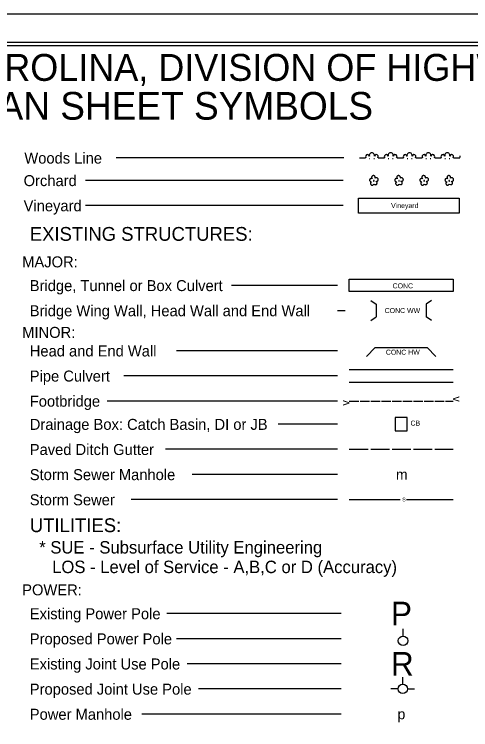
# Model space of a CAD drawing. Extents: x 2078953 to 2080637, y 324331 to 325431.
# Drawn here: x 2079876 to 2080239, y 324862 to 325431 of the extents above; entities that cross this region are included whole.
import ezdxf

# ---------------------------------------------------------------- set-up
doc = ezdxf.new("R2010")
doc.units = 0
for name, color, linetype in [('Sheet Cutting Line CELL', 7, 'Continuous'), ('Sheet Plot Border Inside CELL', 7, 'Continuous'), ('Sheet Plot Border Outside CELL', 7, 'Continuous'), ('Sheet Symbology CELL', 7, 'Continuous')]:
    doc.layers.add(name, color=color, linetype=linetype)

msp = doc.modelspace()

# ---------------------------------------------------------------- linework, layer by layer
at = {"layer": 'Sheet Cutting Line CELL'}
msp.add_line((2080636.7, 325431.07), (2078952.7, 325431.07), dxfattribs=at)
at = {"layer": 'Sheet Plot Border Inside CELL'}
msp.add_lwpolyline([(2078965.7, 324353.52), (2080632.2, 324353.52), (2080632.2, 325408.62), (2078965.7, 325408.62)], close=True, dxfattribs=at)
at = {"layer": 'Sheet Plot Border Outside CELL'}
msp.add_lwpolyline([(2078952.7, 324331.07), (2080636.7, 324331.07), (2080636.7, 325431.07), (2078952.7, 325431.07)], close=True, dxfattribs=at)
at = {"layer": 'Sheet Symbology CELL'}
for p, q in [((2080137.96, 325316.8), (2079956.83, 325316.8)), ((2080150.35, 325316.8), (2080155.35, 325316.8)), ((2080158.3, 325316.3), (2080158.8, 325316.3)), ((2080161.8, 325316.3), (2080162.3, 325316.3)), ((2080165.35, 325316.8), (2080170.35, 325316.8)), ((2080173.3, 325316.3), (2080173.8, 325316.3)), ((2080176.8, 325316.3), (2080177.3, 325316.3)), ((2080180.35, 325316.8), (2080185.35, 325316.8)), ((2080188.3, 325316.3), (2080188.8, 325316.3)), ((2080191.8, 325316.3), (2080192.3, 325316.3)), ((2080195.35, 325316.8), (2080200.35, 325316.8)), ((2080203.3, 325316.3), (2080203.8, 325316.3)), ((2080206.8, 325316.3), (2080207.3, 325316.3)), ((2080210.35, 325316.8), (2080215.35, 325316.8)), ((2080218.3, 325316.3), (2080218.8, 325316.3)), ((2080221.8, 325316.3), (2080222.3, 325316.3)), ((2080225.35, 325316.8), (2080230.35, 325316.8)), ((2080137.39, 325298.87), (2079932.46, 325298.87)), ((2080137.39, 325278.87), (2079932.46, 325278.87)), ((2080133.08, 325215.37), (2080048.65, 325215.37)), ((2080159.53, 325203.23), (2080163.63, 325200.37)), ((2080163.63, 325200.37), (2080163.63, 325190.37)), ((2080207.73, 325203.23), (2080203.63, 325200.37)), ((2080203.63, 325200.37), (2080203.63, 325190.37)), ((2080133.08, 325195.37), (2080139.07, 325195.37)), ((2080159.53, 325187.5), (2080163.63, 325190.37)), ((2080207.73, 325187.5), (2080203.63, 325190.37)), ((2080133.08, 325163.37), (2080004.78, 325163.37)), ((2080155.93, 325158.8), (2080163, 325165.87)), ((2080163, 325165.87), (2080204.25, 325165.87)), ((2080204.25, 325165.87), (2080211.33, 325158.8)), ((2080142.38, 325148.37), (2080224.88, 325148.37)), ((2080133.08, 325143.37), (2079962.89, 325143.37)), ((2080142.38, 325138.37), (2080224.88, 325138.37)), ((2080133.08, 325123.37), (2079949.6, 325123.37)), ((2080142.38, 325123.37), (2080149.88, 325123.37)), ((2080150.88, 325123.37), (2080158.38, 325123.37)), ((2080159.38, 325123.37), (2080166.88, 325123.37)), ((2080167.88, 325123.37), (2080175.38, 325123.37)), ((2080176.38, 325123.37), (2080183.88, 325123.37)), ((2080184.88, 325123.37), (2080192.38, 325123.37)), ((2080193.38, 325123.37), (2080200.88, 325123.37)), ((2080201.88, 325123.37), (2080209.38, 325123.37)), ((2080210.38, 325123.37), (2080217.88, 325123.37)), ((2080218.88, 325123.37), (2080224.88, 325123.37)), ((2080133.08, 325104.94), (2080085.88, 325104.94)), ((2080133.08, 325084.94), (2079996.13, 325084.94)), ((2080142.38, 325084.94), (2080157.38, 325084.94)), ((2080159.38, 325084.94), (2080174.38, 325084.94)), ((2080176.38, 325084.94), (2080191.38, 325084.94)), ((2080193.38, 325084.94), (2080208.38, 325084.94)), ((2080210.38, 325084.94), (2080224.88, 325084.94)), ((2080133.08, 325064.94), (2080017.4, 325064.94)), ((2080133.08, 325044.94), (2079968.88, 325044.94)), ((2080142.38, 325044.94), (2080182.9, 325044.94)), ((2080187.9, 325044.94), (2080224.88, 325044.94)), ((2080135.87, 324954.25), (2079997.17, 324954.25)), ((2080185.09, 324936.37), (2080185.09, 324941.99)), ((2080135.87, 324934.25), (2080004.95, 324934.25)), ((2080135.87, 324914.25), (2080013.35, 324914.25)), ((2080184.88, 324898.02), (2080184.88, 324903.64)), ((2080135.87, 324894.25), (2080022.35, 324894.25)), ((2080181.13, 324894.27), (2080175.5, 324894.27)), ((2080188.63, 324894.27), (2080194.25, 324894.27)), ((2080135.87, 324874.25), (2079977.37, 324874.25))]:
    msp.add_line(p, q, dxfattribs=at)
for points in [[(2080619.7, 325406.07), (2079119.7, 325406.07), (2079119.7, 324357.08), (2080619.7, 324357.08)], [(2080178.82, 325099.62), (2080188.43, 325099.62), (2080188.43, 325110.26), (2080178.82, 325110.26)]]:
    msp.add_lwpolyline(points, close=True, dxfattribs=at)
for points in [[(2080162.84, 325300.62), (2080162.99, 325300.92), (2080163.04, 325301.22), (2080162.99, 325301.52), (2080162.94, 325301.82), (2080162.79, 325302.07), (2080162.64, 325302.32), (2080162.39, 325302.52), (2080162.14, 325302.67), (2080161.79, 325302.77), (2080161.54, 325302.77), (2080161.24, 325302.72), (2080160.94, 325302.62), (2080160.69, 325302.47), (2080160.44, 325302.27), (2080160.29, 325301.97), (2080160.19, 325301.72), (2080160.14, 325301.42), (2080160.14, 325301.12), (2080160.19, 325300.82), (2080160.34, 325300.57), (2080160.54, 325300.27), (2080160.29, 325300.42), (2080159.99, 325300.47), (2080159.69, 325300.47), (2080159.44, 325300.37), (2080159.19, 325300.27), (2080158.94, 325300.07), (2080158.74, 325299.87), (2080158.59, 325299.62), (2080158.54, 325299.37), (2080158.49, 325299.02), (2080158.54, 325298.77), (2080158.64, 325298.52), (2080158.84, 325298.27), (2080158.99, 325298.07), (2080159.24, 325297.92), (2080159.54, 325297.77), (2080159.79, 325297.72), (2080160.09, 325297.72), (2080159.84, 325297.62), (2080159.59, 325297.42), (2080159.44, 325297.22), (2080159.34, 325296.92), (2080159.24, 325296.62), (2080159.24, 325296.37), (2080159.29, 325296.07), (2080159.44, 325295.82), (2080159.59, 325295.57), (2080159.79, 325295.37), (2080160.04, 325295.22), (2080160.29, 325295.12), (2080160.59, 325295.12), (2080160.89, 325295.12), (2080161.14, 325295.17), (2080161.39, 325295.37), (2080161.64, 325295.52), (2080161.89, 325295.97)], [(2080161.99, 325298.87), (2080161.84, 325298.87), (2080161.74, 325298.82), (2080161.64, 325298.77), (2080161.64, 325298.62), (2080161.64, 325298.52), (2080161.74, 325298.42), (2080161.89, 325298.42), (2080161.99, 325298.42), (2080162.09, 325298.52), (2080162.14, 325298.67), (2080162.09, 325298.77), (2080161.99, 325298.87)], [(2080161.89, 325295.97), (2080162.49, 325295.62), (2080162.79, 325295.52), (2080163.09, 325295.47), (2080163.39, 325295.52), (2080163.64, 325295.62), (2080163.89, 325295.77), (2080164.14, 325295.97), (2080164.29, 325296.22), (2080164.39, 325296.47), (2080164.49, 325296.77), (2080164.44, 325297.07), (2080164.39, 325297.37), (2080164.19, 325297.67), (2080164.04, 325297.87), (2080163.79, 325298.02), (2080163.49, 325298.17), (2080163.79, 325298.12), (2080164.14, 325298.12), (2080164.39, 325298.22), (2080164.69, 325298.37), (2080164.94, 325298.52), (2080165.14, 325298.77), (2080165.29, 325299.07), (2080165.34, 325299.37), (2080165.39, 325299.67), (2080165.34, 325299.97), (2080165.24, 325300.27), (2080165.04, 325300.52), (2080164.79, 325300.77), (2080164.54, 325300.92), (2080164.24, 325301.02), (2080163.94, 325301.07), (2080163.64, 325301.07), (2080163.34, 325300.97), (2080163.09, 325300.82), (2080162.84, 325300.62)], [(2080182.84, 325300.62), (2080182.99, 325300.92), (2080183.04, 325301.22), (2080182.99, 325301.52), (2080182.94, 325301.82), (2080182.79, 325302.07), (2080182.64, 325302.32), (2080182.39, 325302.52), (2080182.14, 325302.67), (2080181.79, 325302.77), (2080181.54, 325302.77), (2080181.24, 325302.72), (2080180.94, 325302.62), (2080180.69, 325302.47), (2080180.44, 325302.27), (2080180.29, 325301.97), (2080180.19, 325301.72), (2080180.14, 325301.42), (2080180.14, 325301.12), (2080180.19, 325300.82), (2080180.34, 325300.57), (2080180.54, 325300.27), (2080180.29, 325300.42), (2080179.99, 325300.47), (2080179.69, 325300.47), (2080179.44, 325300.37), (2080179.19, 325300.27), (2080178.94, 325300.07), (2080178.74, 325299.87), (2080178.59, 325299.62), (2080178.54, 325299.37), (2080178.49, 325299.02), (2080178.54, 325298.77), (2080178.64, 325298.52), (2080178.84, 325298.27), (2080178.99, 325298.07), (2080179.24, 325297.92), (2080179.54, 325297.77), (2080179.79, 325297.72), (2080180.09, 325297.72), (2080179.84, 325297.62), (2080179.59, 325297.42), (2080179.44, 325297.22), (2080179.34, 325296.92), (2080179.24, 325296.62), (2080179.24, 325296.37), (2080179.29, 325296.07), (2080179.44, 325295.82), (2080179.59, 325295.57), (2080179.79, 325295.37), (2080180.04, 325295.22), (2080180.29, 325295.12), (2080180.59, 325295.12), (2080180.89, 325295.12), (2080181.14, 325295.17), (2080181.39, 325295.37), (2080181.64, 325295.52), (2080181.89, 325295.97)], [(2080181.99, 325298.87), (2080181.84, 325298.87), (2080181.74, 325298.82), (2080181.64, 325298.77), (2080181.64, 325298.62), (2080181.64, 325298.52), (2080181.74, 325298.42), (2080181.89, 325298.42), (2080181.99, 325298.42), (2080182.09, 325298.52), (2080182.14, 325298.67), (2080182.09, 325298.77), (2080181.99, 325298.87)], [(2080181.89, 325295.97), (2080182.49, 325295.62), (2080182.79, 325295.52), (2080183.09, 325295.47), (2080183.39, 325295.52), (2080183.64, 325295.62), (2080183.89, 325295.77), (2080184.14, 325295.97), (2080184.29, 325296.22), (2080184.39, 325296.47), (2080184.49, 325296.77), (2080184.44, 325297.07), (2080184.39, 325297.37), (2080184.19, 325297.67), (2080184.04, 325297.87), (2080183.79, 325298.02), (2080183.49, 325298.17), (2080183.79, 325298.12), (2080184.14, 325298.12), (2080184.39, 325298.22), (2080184.69, 325298.37), (2080184.94, 325298.52), (2080185.14, 325298.77), (2080185.29, 325299.07), (2080185.34, 325299.37), (2080185.39, 325299.67), (2080185.34, 325299.97), (2080185.24, 325300.27), (2080185.04, 325300.52), (2080184.79, 325300.77), (2080184.54, 325300.92), (2080184.24, 325301.02), (2080183.94, 325301.07), (2080183.64, 325301.07), (2080183.34, 325300.97), (2080183.09, 325300.82), (2080182.84, 325300.62)], [(2080202.84, 325300.62), (2080202.99, 325300.92), (2080203.04, 325301.22), (2080202.99, 325301.52), (2080202.94, 325301.82), (2080202.79, 325302.07), (2080202.64, 325302.32), (2080202.39, 325302.52), (2080202.14, 325302.67), (2080201.79, 325302.77), (2080201.54, 325302.77), (2080201.24, 325302.72), (2080200.94, 325302.62), (2080200.69, 325302.47), (2080200.44, 325302.27), (2080200.29, 325301.97), (2080200.19, 325301.72), (2080200.14, 325301.42), (2080200.14, 325301.12), (2080200.19, 325300.82), (2080200.34, 325300.57), (2080200.54, 325300.27), (2080200.29, 325300.42), (2080199.99, 325300.47), (2080199.69, 325300.47), (2080199.44, 325300.37), (2080199.19, 325300.27), (2080198.94, 325300.07), (2080198.74, 325299.87), (2080198.59, 325299.62), (2080198.54, 325299.37), (2080198.49, 325299.02), (2080198.54, 325298.77), (2080198.64, 325298.52), (2080198.84, 325298.27), (2080198.99, 325298.07), (2080199.24, 325297.92), (2080199.54, 325297.77), (2080199.79, 325297.72), (2080200.09, 325297.72), (2080199.84, 325297.62), (2080199.59, 325297.42), (2080199.44, 325297.22), (2080199.34, 325296.92), (2080199.24, 325296.62), (2080199.24, 325296.37), (2080199.29, 325296.07), (2080199.44, 325295.82), (2080199.59, 325295.57), (2080199.79, 325295.37), (2080200.04, 325295.22), (2080200.29, 325295.12), (2080200.59, 325295.12), (2080200.89, 325295.12), (2080201.14, 325295.17), (2080201.39, 325295.37), (2080201.64, 325295.52), (2080201.89, 325295.97)], [(2080201.99, 325298.87), (2080201.84, 325298.87), (2080201.74, 325298.82), (2080201.64, 325298.77), (2080201.64, 325298.62), (2080201.64, 325298.52), (2080201.74, 325298.42), (2080201.89, 325298.42), (2080201.99, 325298.42), (2080202.09, 325298.52), (2080202.14, 325298.67), (2080202.09, 325298.77), (2080201.99, 325298.87)], [(2080201.89, 325295.97), (2080202.49, 325295.62), (2080202.79, 325295.52), (2080203.09, 325295.47), (2080203.39, 325295.52), (2080203.64, 325295.62), (2080203.89, 325295.77), (2080204.14, 325295.97), (2080204.29, 325296.22), (2080204.39, 325296.47), (2080204.49, 325296.77), (2080204.44, 325297.07), (2080204.39, 325297.37), (2080204.19, 325297.67), (2080204.04, 325297.87), (2080203.79, 325298.02), (2080203.49, 325298.17), (2080203.79, 325298.12), (2080204.14, 325298.12), (2080204.39, 325298.22), (2080204.69, 325298.37), (2080204.94, 325298.52), (2080205.14, 325298.77), (2080205.29, 325299.07), (2080205.34, 325299.37), (2080205.39, 325299.67), (2080205.34, 325299.97), (2080205.24, 325300.27), (2080205.04, 325300.52), (2080204.79, 325300.77), (2080204.54, 325300.92), (2080204.24, 325301.02), (2080203.94, 325301.07), (2080203.64, 325301.07), (2080203.34, 325300.97), (2080203.09, 325300.82), (2080202.84, 325300.62)], [(2080222.84, 325300.62), (2080222.99, 325300.92), (2080223.04, 325301.22), (2080222.99, 325301.52), (2080222.94, 325301.82), (2080222.79, 325302.07), (2080222.64, 325302.32), (2080222.39, 325302.52), (2080222.14, 325302.67), (2080221.79, 325302.77), (2080221.54, 325302.77), (2080221.24, 325302.72), (2080220.94, 325302.62), (2080220.69, 325302.47), (2080220.44, 325302.27), (2080220.29, 325301.97), (2080220.19, 325301.72), (2080220.14, 325301.42), (2080220.14, 325301.12), (2080220.19, 325300.82), (2080220.34, 325300.57), (2080220.54, 325300.27), (2080220.29, 325300.42), (2080219.99, 325300.47), (2080219.69, 325300.47), (2080219.44, 325300.37), (2080219.19, 325300.27), (2080218.94, 325300.07), (2080218.74, 325299.87), (2080218.59, 325299.62), (2080218.54, 325299.37), (2080218.49, 325299.02), (2080218.54, 325298.77), (2080218.64, 325298.52), (2080218.84, 325298.27), (2080218.99, 325298.07), (2080219.24, 325297.92), (2080219.54, 325297.77), (2080219.79, 325297.72), (2080220.09, 325297.72), (2080219.84, 325297.62), (2080219.59, 325297.42), (2080219.44, 325297.22), (2080219.34, 325296.92), (2080219.24, 325296.62), (2080219.24, 325296.37), (2080219.29, 325296.07), (2080219.44, 325295.82), (2080219.59, 325295.57), (2080219.79, 325295.37), (2080220.04, 325295.22), (2080220.29, 325295.12), (2080220.59, 325295.12), (2080220.89, 325295.12), (2080221.14, 325295.17), (2080221.39, 325295.37), (2080221.64, 325295.52), (2080221.89, 325295.97)], [(2080221.99, 325298.87), (2080221.84, 325298.87), (2080221.74, 325298.82), (2080221.64, 325298.77), (2080221.64, 325298.62), (2080221.64, 325298.52), (2080221.74, 325298.42), (2080221.89, 325298.42), (2080221.99, 325298.42), (2080222.09, 325298.52), (2080222.14, 325298.67), (2080222.09, 325298.77), (2080221.99, 325298.87)], [(2080221.89, 325295.97), (2080222.49, 325295.62), (2080222.79, 325295.52), (2080223.09, 325295.47), (2080223.39, 325295.52), (2080223.64, 325295.62), (2080223.89, 325295.77), (2080224.14, 325295.97), (2080224.29, 325296.22), (2080224.39, 325296.47), (2080224.49, 325296.77), (2080224.44, 325297.07), (2080224.39, 325297.37), (2080224.19, 325297.67), (2080224.04, 325297.87), (2080223.79, 325298.02), (2080223.49, 325298.17), (2080223.79, 325298.12), (2080224.14, 325298.12), (2080224.39, 325298.22), (2080224.69, 325298.37), (2080224.94, 325298.52), (2080225.14, 325298.77), (2080225.29, 325299.07), (2080225.34, 325299.37), (2080225.39, 325299.67), (2080225.34, 325299.97), (2080225.24, 325300.27), (2080225.04, 325300.52), (2080224.79, 325300.77), (2080224.54, 325300.92), (2080224.24, 325301.02), (2080223.94, 325301.07), (2080223.64, 325301.07), (2080223.34, 325300.97), (2080223.09, 325300.82), (2080222.84, 325300.62)], [(2080149.79, 325284.87), (2080229.79, 325284.87), (2080229.79, 325272.87), (2080149.79, 325272.87), (2080149.79, 325284.87)], [(2080142.38, 325220.37), (2080224.88, 325220.37), (2080224.88, 325210.37), (2080142.38, 325210.37), (2080142.38, 325220.37)]]:
    msp.add_lwpolyline(points, dxfattribs=at)
for centre in [(2080185.09, 324932.62), (2080184.88, 324894.25)]:
    msp.add_circle(centre, 3.75, dxfattribs=at)
for centre, radius, start, end in [((2080160.3, 325318.82), 2.06, 345.9638, 194.0362), ((2080175.3, 325318.82), 2.06, 345.9638, 194.0362), ((2080190.3, 325318.82), 2.06, 345.9638, 194.0362), ((2080205.3, 325318.82), 2.06, 345.9638, 194.0362), ((2080220.3, 325318.82), 2.06, 345.9638, 194.0362), ((2080156.8, 325317.82), 1.58, 18.435, 219.2315), ((2080163.8, 325317.82), 1.58, 320.7685, 161.5651), ((2080171.8, 325317.82), 1.58, 18.435, 219.2315), ((2080178.8, 325317.82), 1.58, 320.7685, 161.5651), ((2080186.8, 325317.82), 1.58, 18.435, 219.2315), ((2080193.8, 325317.82), 1.58, 320.7685, 161.5651), ((2080201.8, 325317.82), 1.58, 18.435, 219.2315), ((2080208.8, 325317.82), 1.58, 320.7685, 161.5651), ((2080216.8, 325317.82), 1.58, 18.435, 219.2315), ((2080223.8, 325317.82), 1.58, 320.7685, 161.5651), ((2080231.8, 325317.82), 1.58, 156.251, 203.749)]:
    msp.add_arc(centre, radius, start, end, dxfattribs=at)

# ---------------------------------------------------------------- texts
for s, height, p in [('STATE OF NORTH CAROLINA, DIVISION OF HIGHWAYS', 21.419, (2079570.26, 325378.11)), ('CONVENTIONAL  PLAN SHEET SYMBOLS', 22.0323, (2079578.39, 325347.23)), ('Woods Line', 8.75, (2079883.8, 325312.28)), ('Orchard', 8.75, (2079883.23, 325294.35)), ('Vineyard', 8.75, (2079883.23, 325274.35)), ('EXISTING STRUCTURES:', 11, (2079888.12, 325250.82)), ('MAJOR:', 8.75, (2079882.09, 325229.7)), ('Bridge, Tunnel or Box Culvert', 8.75, (2079888.12, 325210.82)), ('CONC', 4, (2080176.82, 325213)), ('Bridge Wing Wall, Head Wall and End Wall', 8.75, (2079888.12, 325190.82)), ('MINOR:', 8.75, (2079882.09, 325173.58)), ('Head and End Wall', 8.75, (2079888.12, 325158.82)), ('Pipe Culvert', 8.75, (2079888.12, 325138.84)), ('Footbridge', 8.75, (2079888.13, 325118.84)), ('Drainage Box: Catch Basin, DI or JB', 8.75, (2079888.13, 325100.4)), ('Paved Ditch Gutter', 8.75, (2079888.13, 325080.39)), ('Storm Sewer Manhole', 8.75, (2079888.13, 325060.39)), ('m', 8.25, (2080179.5, 325060.81)), ('Storm Sewer', 8.75, (2079888.13, 325040.39)), ('S', 3, (2080184.5, 325043.44)), ('UTILITIES:', 11, (2079888.12, 325019.02)), ('POWER:', 8.75, (2079882.09, 324968.72)), ('P', 18.75, (2080175.5, 324944.88)), ('Existing Power Pole', 8.75, (2079888.13, 324949.72)), ('Proposed Power Pole', 8.75, (2079888.13, 324929.72)), ('R', 18.75, (2080175.5, 324904.88)), ('Existing Joint Use Pole', 8.75, (2079888.13, 324909.73)), ('Proposed Joint Use Pole', 8.75, (2079888.14, 324889.72)), ('Power Manhole', 8.75, (2079888.14, 324869.72)), ('p', 8.25, (2080180.75, 324870.13))]:
    msp.add_text(s, height=height, dxfattribs=at).set_placement(p)
for s, height, rotation, p in [('Vineyard', 4, 0, (2080175.61, 325276.87)), ('CONC WW', 4, 0, (2080170.5, 325193.37)), ('CONC HW', 4, 360, (2080171.43, 325160.21)), ('v', 6.6, 270.2409, (2080224.87, 325127.11)), ('v', 6.6, 89.7591, (2080142.37, 325119.64)), ('CB', 4, 360, (2080191.07, 325103.76)), ('* SUE - Subsurface Utility Engineering', 9.9, 360, (2079895.65, 325002)), ('LOS - Level of Service - A,B,C or D (Accuracy) ', 9.9, 360, (2079905.92, 324986.43))]:
    msp.add_text(s, height=height, rotation=rotation, dxfattribs=at).set_placement(p)

doc.saveas('drawing.dxf')
